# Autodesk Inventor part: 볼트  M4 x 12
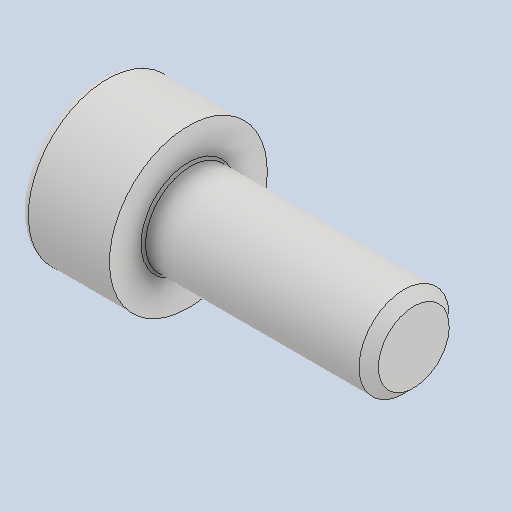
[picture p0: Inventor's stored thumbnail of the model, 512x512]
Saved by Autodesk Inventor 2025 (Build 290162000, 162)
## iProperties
Created: 2024-08
Part Number: 볼트  M4 x 12
Material: 스테인리스강
Description: 6각머리 태핑 나사
Document SubType Name: Modeling
Designer: samsung
Density: 8.08 g/cm^3
Appearance: 기본값
Author: jhkim
Sending System: Autodesk Inventor 2025
Preprocessor: ST-DEVELOPER v20
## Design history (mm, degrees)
feature "Solid1"
node "솔리드1"
